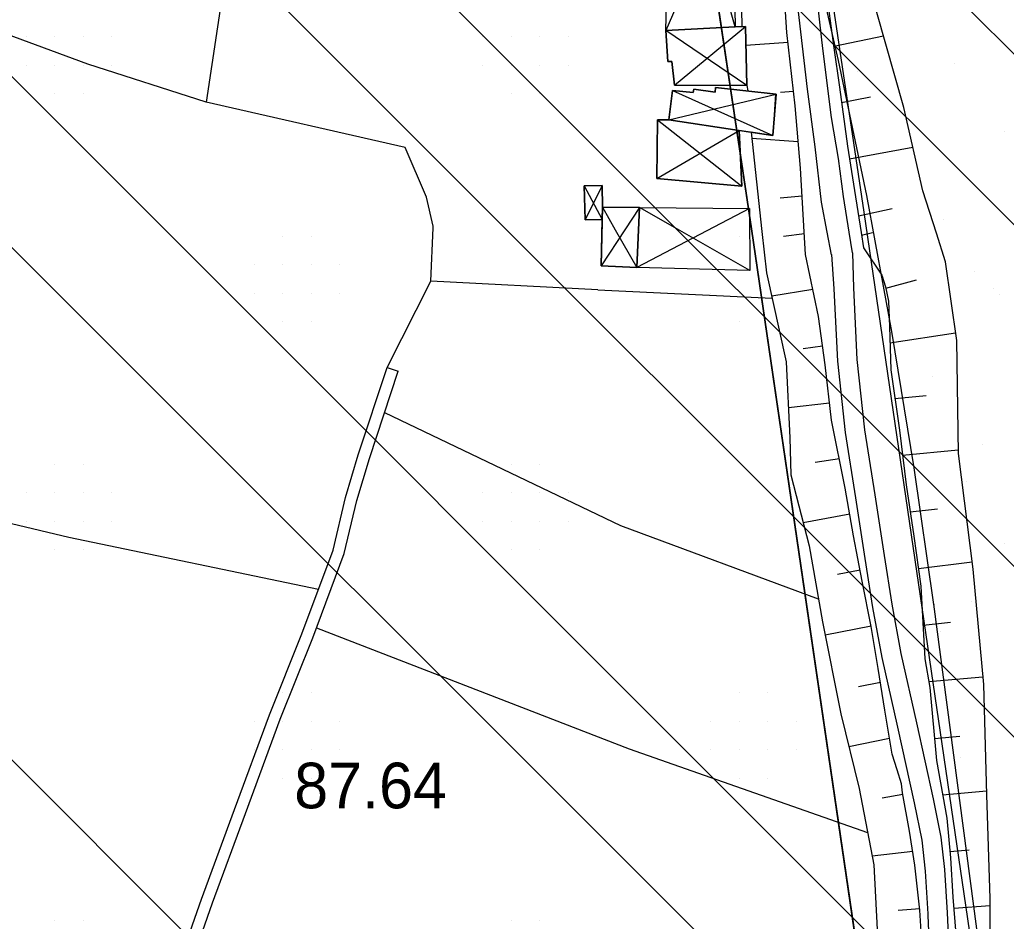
# Model space of a CAD drawing. Extents: x 417995 to 421451, y 4454518 to 4458015.
# Drawn here: x 421037.5 to 421167.2, y 4455713.8 to 4455832.3 of the extents above; entities that cross this region are included whole.
import ezdxf

# ---------------------------------------------------------------- set-up
doc = ezdxf.new("R2010")
doc.units = 0
for name, color, linetype in [('ADAKENARI', 7, 'Continuous'), ('B_Sundurma', 7, 'Continuous'), ('Default', 7, 'Continuous'), ('PL_AYA_PARK_DINLENME', 7, 'Continuous'), ('PL_T_GUNUBIRLIK', 7, 'Continuous'), ('Sev_Sevalti', 7, 'Continuous'), ('Sev_Sevustu', 7, 'Continuous'), ('Sev_Tarama', 7, 'Continuous'), ('Sinir_itirazli_Mulkiyet', 7, 'Continuous'), ('Sinir_Tel_bir_taraf', 7, 'Continuous'), ('SN_TR_SIVILASMA', 7, 'Continuous'), ('TR_PARKALANI', 7, 'Continuous'), ('TRFAT_GUNUBİRLİK', 7, 'Continuous'), ('Y_Kot_Noktasi', 7, 'Continuous'), ('Yol_Toprak_Duz', 7, 'Continuous'), ('Yol_Toprak_Kesik', 7, 'Continuous')]:
    doc.layers.add(name, color=color, linetype=linetype)

# ---------------------------------------------------------------- blocks, each defined once
blk = doc.blocks.new('POINT_DISPLAY')
at = {"layer": 'Default'}
blk.add_line((0, 0), (0, 0), dxfattribs=at)

msp = doc.modelspace()

# ---------------------------------------------------------------- linework, layer by layer
at = {"layer": 'ADAKENARI'}
for p, q in [((421148.54, 4455806.98), (421141.07, 4455857.05)), ((421133.7, 4455804.79), (421126.3, 4455854.38)), ((421167.19, 4455679.67), (421148.54, 4455806.98)), ((421152.1, 4455679.21), (421133.7, 4455804.79))]:
    msp.add_line(p, q, dxfattribs=at)
at = {"layer": 'B_Sundurma'}
for p, q in [((421130.55, 4455849.48), (421122.45, 4455830.84)), ((421131.55, 4455831.35), (421126.68, 4455849.03)), ((421133.1, 4455823.65), (421122.45, 4455830.84)), ((421123.59, 4455823.68), (421132.92, 4455831.38)), ((421123.31, 4455822.99), (421136.5, 4455817.05)), ((421122.83, 4455819.12), (421136.95, 4455822.5)), ((421121.35, 4455819.11), (421132.44, 4455810.4)), ((421121.28, 4455811.4), (421132.09, 4455817.72)), ((421111.71, 4455810.45), (421114.08, 4455806.02)), ((421114.08, 4455810.47), (421111.86, 4455805.98)), ((421114.12, 4455807.62), (421115.81, 4455804.65)), ((421119, 4455807.6), (421117.05, 4455804.64)), ((421124.3, 4455804.56), (421119, 4455807.6)), ((421133.45, 4455807.45), (421127.86, 4455804.52)), ((421117.05, 4455804.64), (421113.95, 4455799.92)), ((421115.81, 4455804.65), (421118.64, 4455799.69)), ((421127.86, 4455804.52), (421118.64, 4455799.69)), ((421133.5, 4455799.29), (421124.3, 4455804.56))]:
    msp.add_line(p, q, dxfattribs=at)
for points in [[(421130.55, 4455849.48), (421131.18, 4455846.27), (421131.47, 4455840.03), (421131.46, 4455836.01), (421131.55, 4455831.35), (421122.45, 4455830.84), (421122.57, 4455836.2), (421123.85, 4455836.28), (421124, 4455839.37), (421125.38, 4455839.57), (421125.37, 4455841.25), (421126.64, 4455841.39), (421126.67, 4455844.19), (421125.29, 4455844.72), (421125.62, 4455846.15), (421126.5, 4455846.19), (421126.68, 4455849.03)], [(421130.55, 4455849.48), (421131.18, 4455846.27), (421131.47, 4455840.03), (421131.46, 4455836.01), (421131.55, 4455831.35), (421122.45, 4455830.84), (421122.57, 4455836.2), (421123.85, 4455836.28), (421124, 4455839.37), (421125.38, 4455839.57), (421125.37, 4455841.25), (421126.64, 4455841.39), (421126.67, 4455844.19), (421125.29, 4455844.73), (421125.62, 4455846.15), (421126.5, 4455846.19), (421126.68, 4455849.03)], [(421123.59, 4455823.68), (421133.1, 4455823.65), (421132.92, 4455831.38), (421131.55, 4455831.35), (421122.45, 4455830.84), (421122.7, 4455826.79), (421123.25, 4455826.8)], [(421123.59, 4455823.68), (421123.25, 4455826.8), (421122.7, 4455826.79), (421122.45, 4455830.84), (421131.55, 4455831.35), (421132.92, 4455831.38), (421133.1, 4455823.65)], [(421123.31, 4455822.99), (421122.83, 4455819.12), (421136.5, 4455817.05), (421136.95, 4455822.5), (421128.97, 4455823.38), (421128.94, 4455822.75), (421126.13, 4455823.16), (421126.04, 4455822.72)], [(421132.09, 4455817.72), (421122.83, 4455819.12), (421123.31, 4455822.99), (421126.04, 4455822.72), (421126.13, 4455823.16), (421128.94, 4455822.75), (421128.97, 4455823.38), (421136.95, 4455822.5), (421136.5, 4455817.05)], [(421122.83, 4455819.12), (421121.35, 4455819.11), (421121.28, 4455811.4), (421132.44, 4455810.4), (421132.09, 4455817.72)], [(421132.09, 4455817.72), (421132.44, 4455810.4), (421121.28, 4455811.4), (421121.35, 4455819.11), (421122.83, 4455819.12)], [(421114.12, 4455807.62), (421114.08, 4455810.47), (421111.71, 4455810.45), (421111.86, 4455805.98), (421114.08, 4455806.02)], [(421114.12, 4455807.62), (421114.08, 4455806.02), (421111.86, 4455805.98), (421111.71, 4455810.45), (421114.08, 4455810.47)], [(421119, 4455807.6), (421114.12, 4455807.62), (421113.95, 4455799.92), (421118.64, 4455799.69)], [(421119, 4455807.6), (421118.64, 4455799.69), (421113.95, 4455799.92), (421114.08, 4455806.02), (421114.12, 4455807.62)], [(421133.45, 4455807.45), (421133.5, 4455799.29), (421118.64, 4455799.69), (421119, 4455807.6)], [(421133.45, 4455807.45), (421133.5, 4455799.29), (421118.64, 4455799.69), (421119, 4455807.6)]]:
    msp.add_lwpolyline(points, close=True, dxfattribs=at)
at = {"layer": 'PL_AYA_PARK_DINLENME'}
msp.add_lwpolyline([(421164.19, 4455706.15), (421157.68, 4455755.43), (421157.68, 4455755.42), (421155.11, 4455773.39), (421152.17, 4455791.3), (421148.85, 4455809.15), (421145.15, 4455826.92), (421141.09, 4455844.61), (421136.64, 4455862.22), (421131.83, 4455879.72), (421126.66, 4455897.12), (421121.11, 4455914.4), (421115.21, 4455931.57), (421108.94, 4455948.61), (421102.32, 4455965.51), (421095.34, 4455982.27), (421088.01, 4455998.87), (421080.33, 4456015.32)], dxfattribs=at)
at = {"layer": 'PL_T_GUNUBIRLIK'}
msp.add_lwpolyline([(421067.57, 4456024.2), (421099.86, 4455958.61), (421115.11, 4455906.97), (421126.3, 4455854.38), (421133.7, 4455804.79), (421152.1, 4455679.21), (421144.29, 4455586.77), (421139.27, 4455582.57), (421022.63, 4455660.74)], dxfattribs=at)
at = {"layer": 'Sev_Sevalti'}
for points in [[(421158.02, 4455804.21), (421156.22, 4455809.77), (421153.74, 4455820.76), (421150.18, 4455833.21), (421147.23, 4455841.2), (421145.05, 4455848.75), (421144.18, 4455858.34), (421143.1, 4455864.46), (421141.7, 4455871.5), (421142.73, 4455875.81), (421143.32, 4455880.06), (421142.74, 4455884.06), (421141.03, 4455891.1)], [(421132.2, 4455875.55), (421132.16, 4455871.85), (421133.17, 4455862.25), (421134.32, 4455859.05), (421134.02, 4455851.84), (421132.27, 4455851.91), (421132.18, 4455844.95), (421132.45, 4455831.37), (421132.92, 4455831.38), (421133.1, 4455823.65), (421133.23, 4455822.91), (421136.88, 4455822.5), (421136.5, 4455817.05), (421133.66, 4455817.48), (421135.09, 4455804.45)], [(421135.09, 4455804.45), (421135.69, 4455799), (421138.29, 4455787.32), (421138.75, 4455777.33), (421138.89, 4455772.46), (421141.28, 4455763.12), (421143.03, 4455753.13), (421145.47, 4455741.05), (421147.85, 4455731.2), (421149.8, 4455721.2), (421150.25, 4455712.7)], [(421165.05, 4455704.79), (421165.1, 4455716.77), (421164.63, 4455730.4), (421164.24, 4455744.87), (421162.85, 4455760.04), (421160.9, 4455775.25), (421160.68, 4455790.1), (421159.23, 4455800.46), (421158.02, 4455804.21)]]:
    msp.add_lwpolyline(points, dxfattribs=at)
at = {"layer": 'Sev_Sevustu'}
for points in [[(421141.03, 4455891.1), (421138.34, 4455888.5), (421138.16, 4455883.06), (421138.29, 4455879.59), (421138.24, 4455873.26), (421138.48, 4455867.86), (421139.81, 4455860.64), (421140.59, 4455855.31), (421141.28, 4455849.39), (421142.4, 4455843.03), (421143.45, 4455836.69), (421144.55, 4455828.59), (421145.26, 4455823.4), (421146.34, 4455815.64), (421147.24, 4455809.84), (421148.13, 4455804.31)], [(421140.65, 4455804.39), (421140.14, 4455812.75), (421139.43, 4455820.97), (421138.37, 4455830.59), (421137.74, 4455840.16), (421137.39, 4455844.63), (421136.58, 4455852.64), (421136.07, 4455856.79), (421135.53, 4455861.08), (421134.92, 4455864.75), (421134.24, 4455868.58), (421133.57, 4455872.5), (421133.01, 4455875.63), (421132.2, 4455875.55)], [(421156.29, 4455708.2), (421155.85, 4455715.22), (421155.17, 4455721.13), (421154.49, 4455725.62), (421153.58, 4455730.63), (421153.41, 4455731.85), (421152.86, 4455733.68), (421152.2, 4455735.73), (421151.23, 4455741.5), (421150.36, 4455746.99), (421149.43, 4455752.52), (421148.24, 4455758.48), (421147.14, 4455764.43), (421146.04, 4455770.7), (421144.22, 4455779.64), (421143.39, 4455786.9), (421142.53, 4455793.25), (421140.83, 4455801.4), (421140.65, 4455804.39)], [(421148.13, 4455804.31), (421148.45, 4455802.27), (421150.83, 4455798.7), (421151.33, 4455797.16), (421151.74, 4455795.27), (421151.86, 4455791.95), (421152.01, 4455786.27), (421153.16, 4455778.33), (421154.04, 4455771.13), (421155.06, 4455764.41), (421155.97, 4455757.81), (421156.5, 4455748.28), (421157.17, 4455744.5), (421158.03, 4455734.91), (421159.38, 4455727.3), (421159.88, 4455722.12), (421160.19, 4455716.95), (421160.97, 4455707.2)]]:
    msp.add_lwpolyline(points, dxfattribs=at)
at = {"layer": 'Sev_Tarama'}
for p, q in [((421138.51, 4455829.29), (421132.98, 4455828.88)), ((421144.52, 4455828.82), (421151.06, 4455830.14)), ((421139.22, 4455822.82), (421137.53, 4455822.72)), ((421145.54, 4455821.41), (421149.34, 4455822.13)), ((421139.84, 4455816.24), (421133.75, 4455816.66)), ((421146.6, 4455813.99), (421154.92, 4455815.52)), ((421140.36, 4455809.1), (421137.5, 4455808.81)), ((421147.77, 4455806.5), (421152.22, 4455807.45)), ((421140.66, 4455804.15), (421137.93, 4455803.8)), ((421148.18, 4455803.94), (421149.61, 4455804.29)), ((421151.37, 4455797), (421155.39, 4455798.08)), ((421141.79, 4455796.8), (421136.37, 4455795.93)), ((421151.91, 4455789.81), (421160.54, 4455791.1)), ((421143.06, 4455789.36), (421140.52, 4455789.03)), ((421152.56, 4455782.5), (421156.67, 4455782.88)), ((421143.97, 4455781.89), (421138.57, 4455781.27)), ((421153.56, 4455775.05), (421160.89, 4455775.75)), ((421145.26, 4455774.56), (421142.06, 4455774.09)), ((421146.64, 4455767.29), (421140.51, 4455766.12)), ((421154.58, 4455767.58), (421158.18, 4455767.99)), ((421155.65, 4455760.13), (421162.73, 4455761.02)), ((421147.98, 4455759.9), (421145.01, 4455759.35)), ((421156.26, 4455752.69), (421159.86, 4455753.08)), ((421149.42, 4455752.55), (421143.38, 4455751.39)), ((421150.65, 4455745.17), (421147.76, 4455744.59)), ((421157.03, 4455745.27), (421164.14, 4455745.91)), ((421151.86, 4455737.77), (421146.52, 4455736.68)), ((421157.77, 4455737.81), (421161.09, 4455738.11)), ((421158.83, 4455730.37), (421164.61, 4455730.89)), ((421153.62, 4455730.41), (421150.9, 4455729.95)), ((421154.9, 4455722.92), (421149.59, 4455722.31)), ((421159.8, 4455722.94), (421162.33, 4455723.15)), ((421155.83, 4455715.41), (421152.98, 4455715.19)), ((421160.3, 4455715.47), (421165.1, 4455715.83))]:
    msp.add_line(p, q, dxfattribs=at)
at = {"layer": 'Sinir_itirazli_Mulkiyet'}
for points in [[(421085.83, 4455786.57), (421091.58, 4455797.93)], [(421085.83, 4455786.57), (421087.27, 4455786.1)], [(421085.47, 4455780.64), (421116.51, 4455765.8), (421142.49, 4455756.17)], [(421016.54, 4455770.77), (421043.98, 4455764.25), (421076.81, 4455757.42)], [(421076.53, 4455752.33), (421117.63, 4455736.45), (421148.98, 4455725.42)]]:
    msp.add_lwpolyline(points, dxfattribs=at)
at = {"layer": 'Sinir_Tel_bir_taraf'}
for points in [[(421083.61, 4456006.02), (421083.88, 4456000.91), (421083.88, 4455994.81), (421083.36, 4455984.23), (421082.79, 4455975.59), (421082.1, 4455964.89), (421079.21, 4455940.24), (421076.33, 4455921.06), (421073.53, 4455902.15), (421070.23, 4455874.23), (421070.15, 4455872.18), (421066.5, 4455851.21), (421062.03, 4455821.45), (421046.49, 4455826.44), (421026.96, 4455833.62)], [(421091.87, 4455804.9), (421091.88, 4455805.12), (421090.99, 4455808.96), (421088.17, 4455815.49), (421062.03, 4455821.45)], [(421113.5, 4455796.78), (421091.58, 4455797.93), (421091.87, 4455804.9)], [(421113.5, 4455796.78), (421136.43, 4455795.67)]]:
    msp.add_lwpolyline(points, dxfattribs=at)
at = {"layer": 'SN_TR_SIVILASMA'}
for p, q in [((421273.94, 4455722.03), (420248.84, 4456747.14)), ((421273.71, 4455699.81), (420266.8, 4456706.72)), ((421273.25, 4455655.37), (420276.01, 4456652.61)), ((421273.02, 4455633.15), (420276.28, 4456629.89)), ((421272.55, 4455588.71), (420264.03, 4456597.24)), ((421272.32, 4455566.5), (420257.91, 4456580.91)), ((421271.63, 4455499.84), (420239.54, 4456531.93))]:
    msp.add_line(p, q, dxfattribs=at)
at = {"layer": 'TRFAT_GUNUBİRLİK'}
for p, q in [((421038.35, 4455830.07), (421038.35, 4455830.07)), ((421042.1, 4455830.07), (421042.1, 4455830.07)), ((421045.85, 4455830.07), (421045.85, 4455830.07)), ((421049.6, 4455830.07), (421049.6, 4455830.07)), ((421098.35, 4455830.07), (421098.35, 4455830.07)), ((421102.1, 4455830.07), (421102.1, 4455830.07)), ((421105.85, 4455830.07), (421105.85, 4455830.07)), ((421109.6, 4455830.07), (421109.6, 4455830.07)), ((421038.35, 4455826.32), (421038.35, 4455826.32)), ((421042.1, 4455826.32), (421042.1, 4455826.32)), ((421045.85, 4455826.32), (421045.85, 4455826.32)), ((421049.6, 4455826.32), (421049.6, 4455826.32)), ((421098.35, 4455826.32), (421098.35, 4455826.32)), ((421102.1, 4455826.32), (421102.1, 4455826.32)), ((421105.85, 4455826.32), (421105.85, 4455826.32)), ((421109.6, 4455826.32), (421109.6, 4455826.32)), ((421042.1, 4455822.57), (421042.1, 4455822.57)), ((421045.85, 4455822.57), (421045.85, 4455822.57)), ((421102.1, 4455822.57), (421102.1, 4455822.57)), ((421105.85, 4455822.57), (421105.85, 4455822.57)), ((421072.1, 4455803.82), (421072.1, 4455803.82)), ((421075.85, 4455803.82), (421075.85, 4455803.82)), ((421132.1, 4455803.82), (421132.1, 4455803.82)), ((421068.35, 4455800.07), (421068.35, 4455800.07)), ((421072.1, 4455800.07), (421072.1, 4455800.07)), ((421075.85, 4455800.07), (421075.85, 4455800.07)), ((421079.6, 4455800.07), (421079.6, 4455800.07)), ((421128.35, 4455800.07), (421128.35, 4455800.07)), ((421132.1, 4455800.07), (421132.1, 4455800.07)), ((421068.35, 4455796.32), (421068.35, 4455796.32)), ((421072.1, 4455796.32), (421072.1, 4455796.32)), ((421075.85, 4455796.32), (421075.85, 4455796.32)), ((421079.6, 4455796.32), (421079.6, 4455796.32)), ((421128.35, 4455796.32), (421128.35, 4455796.32)), ((421132.1, 4455796.32), (421132.1, 4455796.32)), ((421072.1, 4455792.57), (421072.1, 4455792.57)), ((421075.85, 4455792.57), (421075.85, 4455792.57)), ((421132.1, 4455792.57), (421132.1, 4455792.57)), ((421042.1, 4455773.82), (421042.1, 4455773.82)), ((421045.85, 4455773.82), (421045.85, 4455773.82)), ((421102.1, 4455773.82), (421102.1, 4455773.82)), ((421105.85, 4455773.82), (421105.85, 4455773.82)), ((421038.35, 4455770.07), (421038.35, 4455770.07)), ((421042.1, 4455770.07), (421042.1, 4455770.07)), ((421045.85, 4455770.07), (421045.85, 4455770.07)), ((421049.6, 4455770.07), (421049.6, 4455770.07)), ((421098.35, 4455770.07), (421098.35, 4455770.07)), ((421102.1, 4455770.07), (421102.1, 4455770.07)), ((421105.85, 4455770.07), (421105.85, 4455770.07)), ((421109.6, 4455770.07), (421109.6, 4455770.07)), ((421038.35, 4455766.32), (421038.35, 4455766.32)), ((421042.1, 4455766.32), (421042.1, 4455766.32)), ((421045.85, 4455766.32), (421045.85, 4455766.32)), ((421049.6, 4455766.32), (421049.6, 4455766.32)), ((421098.35, 4455766.32), (421098.35, 4455766.32)), ((421102.1, 4455766.32), (421102.1, 4455766.32)), ((421105.85, 4455766.32), (421105.85, 4455766.32)), ((421109.6, 4455766.32), (421109.6, 4455766.32)), ((421042.1, 4455762.57), (421042.1, 4455762.57)), ((421045.85, 4455762.57), (421045.85, 4455762.57)), ((421102.1, 4455762.57), (421102.1, 4455762.57)), ((421105.85, 4455762.57), (421105.85, 4455762.57)), ((421072.1, 4455743.82), (421072.1, 4455743.82)), ((421075.85, 4455743.82), (421075.85, 4455743.82)), ((421132.1, 4455743.82), (421132.1, 4455743.82)), ((421135.85, 4455743.82), (421135.85, 4455743.82)), ((421068.35, 4455740.07), (421068.35, 4455740.07)), ((421072.1, 4455740.07), (421072.1, 4455740.07)), ((421075.85, 4455740.07), (421075.85, 4455740.07)), ((421079.6, 4455740.07), (421079.6, 4455740.07)), ((421128.35, 4455740.07), (421128.35, 4455740.07)), ((421132.1, 4455740.07), (421132.1, 4455740.07)), ((421135.85, 4455740.07), (421135.85, 4455740.07)), ((421139.6, 4455740.07), (421139.6, 4455740.07)), ((421068.35, 4455736.32), (421068.35, 4455736.32)), ((421072.1, 4455736.32), (421072.1, 4455736.32)), ((421075.85, 4455736.32), (421075.85, 4455736.32)), ((421079.6, 4455736.32), (421079.6, 4455736.32)), ((421128.35, 4455736.32), (421128.35, 4455736.32)), ((421132.1, 4455736.32), (421132.1, 4455736.32)), ((421135.85, 4455736.32), (421135.85, 4455736.32)), ((421139.6, 4455736.32), (421139.6, 4455736.32)), ((421072.1, 4455732.57), (421072.1, 4455732.57)), ((421075.85, 4455732.57), (421075.85, 4455732.57)), ((421132.1, 4455732.57), (421132.1, 4455732.57)), ((421135.85, 4455732.57), (421135.85, 4455732.57)), ((421042.1, 4455713.82), (421042.1, 4455713.82)), ((421045.85, 4455713.82), (421045.85, 4455713.82)), ((421102.1, 4455713.82), (421102.1, 4455713.82)), ((421105.85, 4455713.82), (421105.85, 4455713.82))]:
    msp.add_line(p, q, dxfattribs=at)
at = {"layer": 'Yol_Toprak_Duz'}
for points in [[(421143.67, 4455804.36), (421142.93, 4455808.3), (421142.06, 4455815.58), (421141.06, 4455823.15), (421139.75, 4455834.46), (421138.85, 4455842.79), (421137.52, 4455851.85), (421136.4, 4455859.66), (421135.05, 4455868.73), (421133.74, 4455874.59), (421133.31, 4455875.98), (421132.91, 4455877.24)], [(421144.24, 4455801.35), (421143.67, 4455804.36)], [(421144.23, 4455801.4), (421144.55, 4455796.89), (421145.01, 4455787.4), (421146.01, 4455778.02), (421147.39, 4455769.41), (421148.61, 4455761.44), (421149.63, 4455755.01), (421150.84, 4455748.46), (421152.9, 4455739.27), (421155.11, 4455729.34), (421156.09, 4455724.43), (421156.53, 4455720.37), (421156.89, 4455714.74), (421156.9, 4455714.56)], [(421046.24, 4455671.01), (421047.95, 4455674.42), (421052.34, 4455685.49), (421055.75, 4455696.54), (421059.25, 4455705.88), (421062.86, 4455716.17), (421067.2, 4455727.92), (421071.77, 4455740.35), (421076.04, 4455751.01), (421080.19, 4455762.1), (421081.82, 4455769.09), (421083.48, 4455774.61), (421087.27, 4455786.1)], [(421159.45, 4455714.88), (421159.45, 4455714.87), (421159.77, 4455707.29), (421159.95, 4455703.08), (421160.4, 4455700), (421161.35, 4455693.99), (421162.09, 4455686.94), (421162.27, 4455680.09), (421161.93, 4455674.15), (421161.62, 4455666.53), (421161.18, 4455657.71), (421160.93, 4455645.13), (421160.47, 4455638.63), (421159.52, 4455630.01), (421158.31, 4455619.02), (421156.99, 4455607.84), (421155.74, 4455597.54), (421154.66, 4455590.06), (421153.01, 4455581.6), (421151.67, 4455574.29), (421150.64, 4455571.15), (421149.12, 4455568.22)]]:
    msp.add_lwpolyline(points, dxfattribs=at)
at = {"layer": 'Yol_Toprak_Kesik'}
for points in [[(421146.57, 4455804.33), (421145.81, 4455809.06), (421145.15, 4455814.02), (421144.23, 4455819.43), (421143.09, 4455828.51), (421142.05, 4455837.8), (421140.86, 4455847.41), (421139.71, 4455855.08), (421138.53, 4455863.35), (421137.37, 4455869.74), (421136.42, 4455874.69), (421135.55, 4455879), (421134.47, 4455884.01), (421133.97, 4455887.44)], [(421147, 4455801.63), (421146.57, 4455804.33)], [(421147, 4455801.63), (421147.11, 4455797.05), (421147.56, 4455787.6), (421148.55, 4455778.36), (421149.92, 4455769.81), (421151.14, 4455761.83), (421152.16, 4455755.45), (421153.35, 4455748.98), (421155.4, 4455739.83), (421157.61, 4455729.87), (421158.62, 4455724.82), (421159.08, 4455720.59), (421159.45, 4455714.88)], [(421044.88, 4455671.69), (421046.56, 4455675.04), (421050.9, 4455686), (421054.31, 4455697.03), (421057.82, 4455706.4), (421061.43, 4455716.68), (421065.77, 4455728.45), (421070.35, 4455740.89), (421074.61, 4455751.56), (421078.73, 4455762.54), (421080.34, 4455769.48), (421082.03, 4455775.07), (421085.83, 4455786.57)], [(421156.9, 4455714.56), (421157.21, 4455707.18), (421157.39, 4455702.84), (421157.86, 4455699.61), (421158.81, 4455693.65), (421159.53, 4455686.77), (421159.7, 4455680.13), (421159.37, 4455674.28), (421159.06, 4455666.65), (421158.62, 4455657.81), (421158.36, 4455645.24), (421157.92, 4455638.86), (421156.97, 4455630.29), (421155.77, 4455619.31), (421154.45, 4455608.15), (421153.2, 4455597.88), (421152.13, 4455590.49), (421150.49, 4455582.08), (421149.18, 4455574.92), (421148.27, 4455572.14), (421147.62, 4455570.89)]]:
    msp.add_lwpolyline(points, dxfattribs=at)

# ---------------------------------------------------------------- block references
at = {"layer": 'TR_PARKALANI', "xscale": 0.1, "yscale": 0.10000000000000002}
for p in [(421160.34, 4455826.52), (421147.61, 4455825.44), (421155.03, 4455818.44), (421167, 4455817.54), (421152.23, 4455814.94), (421158.89, 4455805.96), (421163.06, 4455799.24), (421165.55, 4455796.98), (421166.33, 4455796.14), (421157.44, 4455785.4), (421164.1, 4455776.42), (421161.98, 4455771.52), (421167.03, 4455763.4), (421162.65, 4455755.85), (421158.51, 4455751.82), (421161.2, 4455735.29)]:
    msp.add_blockref('POINT_DISPLAY', p, dxfattribs=at)

# ---------------------------------------------------------------- texts
at = {"layer": 'Y_Kot_Noktasi'}
msp.add_text('87.64', height=6, dxfattribs=at).set_placement((421073.6, 4455728.61))

doc.saveas('drawing.dxf')
